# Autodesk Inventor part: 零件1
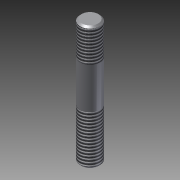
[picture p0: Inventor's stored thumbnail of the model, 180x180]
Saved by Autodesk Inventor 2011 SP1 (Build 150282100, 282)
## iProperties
Created: 2014-02
Part Number: 零件1
Document SubType Name: Modeling
Designer: yn
Density: 1 g/cm^3
Author: yn
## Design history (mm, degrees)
sketch "草图1"
  geometry: C1 r 6 at (0, 0); 1 further point
  constraints: 1 centre point, 1 coincident
  dimensions: "d0" = 12 diameter of C1
extrude "拉伸1" new body sketch "草图1" distance "d1" = 75; taper "d2" = 0 deg
feature "螺纹1" dims "d6" = 30, "d7" = 0
feature "螺纹2" dims "d8" = 20, "d9" = 0
chamfer "倒角2" distance "d10" = 1; stored, may be unused: second distance "d11" = 2, angle "d12" = 45 deg
node "实体1"
